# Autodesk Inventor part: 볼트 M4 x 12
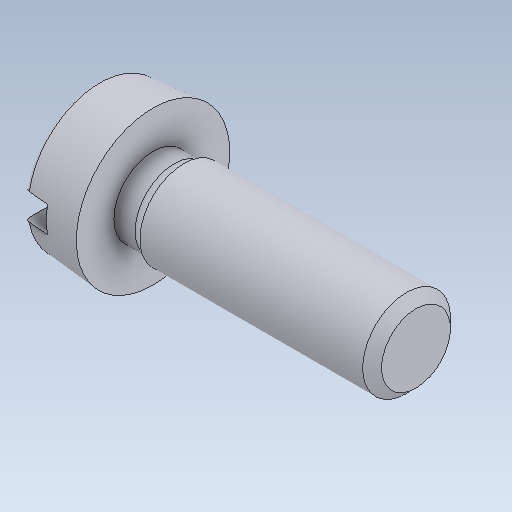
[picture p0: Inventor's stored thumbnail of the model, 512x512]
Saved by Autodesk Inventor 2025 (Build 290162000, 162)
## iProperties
Created: 2024-07
Part Number: 볼트 M4 x 12
Material: 강철, 연강
Description: 6각머리 태핑 나사
Document SubType Name: Modeling
Designer: 미서니
Density: 7.85 g/cm^3
Appearance: 기본값
Author: jhkim
Sending System: Autodesk Inventor 2025
Preprocessor: ST-DEVELOPER v20
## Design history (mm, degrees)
feature "Solid1"
node "솔리드1"
